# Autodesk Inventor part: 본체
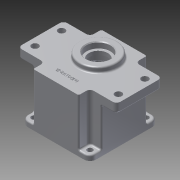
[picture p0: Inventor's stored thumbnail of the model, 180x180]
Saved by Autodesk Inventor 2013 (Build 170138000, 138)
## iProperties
Created: 2015-07
Part Number: 본체
Material: 알루미늄 6061
Document SubType Name: Modeling
Designer: user
Density: 1 g/cm^3
Author: user
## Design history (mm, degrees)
sketch "스케치1"
  geometry: L1 (-37, 45)-(37, 45); L2 (45, 37)-(45, -37); L3 (37, -45)-(-37, -45); L4 (-45, -37)-(-45, 37); L5 (-45, 45)-(45, -45); L6 (45, 45)-(-45, -45); A1 r 8 centre (-37, 37) between (-37, 45) and (-45, 37); A2 r 8 centre (37, 37) between (45, 37) and (37, 45); A3 r 8 centre (37, -37) between (37, -45) and (45, -37); A4 r 8 centre (-37, -37) between (-45, -37) and (-37, -45); 1 further point
  constraints: 12 end point, 8 point on circle, 8 point on line, 8 tangent, 4 centre point, 3 equal radius, 2 midpoint, 2 parallel, 1 horizontal, 1 perpendicular
  dimensions: "d0" = 90 distance of L5.end L6.end; "d1" = 90 distance of L6.start L5.end; "d2" = 8 radius of A1
extrude "돌출1" new body sketch "스케치1" distance "d3" = 70; taper "d4" = 0 deg
sketch "스케치2"
  geometry: L1 (30, 35)-(30, 61.465); L2 (35, 30)-(85.912, 30); L3 (30, 61.465)-(85.912, 30); L4 (37, 45)-(-37, 45) reference; L5 (0, 0)-(0, 77.772); L6 (-30, 35)-(-30, 61.465); L7 (-35, 30)-(-85.912, 30); L8 (-30, 61.465)-(-85.912, 30); L9 (0, 0)-(60.456, 0); L10 (30, -35)-(30, -61.465); L11 (30, -61.465)-(85.912, -30); L12 (35, -30)-(85.912, -30); L13 (-30, -61.465)-(-85.912, -30); L14 (-30, -35)-(-30, -61.465); L15 (-35, -30)-(-85.912, -30); A1 r 5 centre (35, 35) between (30, 35) and (35, 30); A2 r 5 centre (-35, 35) between (-35, 30) and (-30, 35); A3 r 5 centre (35, -35) between (35, -30) and (30, -35); A4 r 5 centre (-35, -35) between (-30, -35) and (-35, -30)
  constraints: 28 end point, 15 symmetric about line, 8 point on circle, 4 centre point, 2 perpendicular, 2 tangent, 1 parallel, 3 other
  dimensions: "d7" = 5 radius of A1
extrude "돌출4" cut sketch "스케치2" distance "d15" = 63; taper "d16" = 0 deg
sketch "스케치6"
  geometry: L1 (-60, 30)-(60, 30); L2 (65, 25)-(65, -25); L3 (60, -30)-(-60, -30); L4 (-65, -25)-(-65, 25); L5 (-65, 30)-(65, -30); L6 (65, 30)-(-65, -30); L7 (-55, 17.5)-(55, -17.5); L8 (55, 17.5)-(-55, -17.5); C1 r 4.5 at (55, 17.5); C2 r 4.5 at (-55, 17.5); C3 r 4.5 at (-55, -17.5); C4 r 4.5 at (55, -17.5); A1 r 5 centre (60, 25) between (65, 25) and (60, 30); A2 r 5 centre (-60, 25) between (-60, 30) and (-65, 25); A3 r 5 centre (-60, -25) between (-65, -25) and (-60, -30); A4 r 5 centre (60, -25) between (60, -30) and (65, -25); 1 further point
  constraints: 16 end point, 8 centre point, 8 point on circle, 8 point on line, 8 tangent, 4 coincident, 4 midpoint, 3 equal radius, 2 parallel, 1 horizontal, 1 perpendicular
  dimensions: "d17" = 130 distance of L5.end L6.end; "d18" = 60 distance of L6.start L5.end; "d19" = 5 radius of A1; "d20" = 110 distance of L7.end L8.end; "d21" = 35 distance of L8.start L7.end; "d22" = 9 diameter of C1; "d23" = 9 diameter of C2; "d24" = 9 diameter of C3; "d25" = 9 diameter of C4
extrude "돌출5" join sketch "스케치6" distance "d26" = 12; taper "d27" = 0 deg
sketch "스케치7"
  geometry: C1 r 3.5 at (-37, 37); C2 r 3.5 at (37, 37); C3 r 3.5 at (-37, -37); C4 r 3.5 at (37, -37); A1 r 8 centre (37, 37) between (45, 37) and (37, 45) reference; A2 r 8 centre (-37, 37) between (-37, 45) and (-45, 37) reference; A3 r 8 centre (-37, -37) between (-45, -37) and (-37, -45) reference; A4 r 8 centre (37, -37) between (37, -45) and (45, -37) reference; 1 further point
  constraints: 4 centre point, 4 coincident
  dimensions: "d28" = 7 diameter of C1; "d29" = 7 diameter of C2; "d30" = 7 diameter of C3; "d31" = 7 diameter of C4
extrude "돌출6" cut sketch "스케치7" stored distance "d32" = 12; taper "d33" = 0 deg
sketch "스케치8"
  geometry: C1 r 40 at (0, 0); 1 further point
  constraints: 1 centre point, 1 coincident
  dimensions: "d34" = 80 diameter of C1
extrude "돌출7" cut sketch "스케치8" distance "d35" = 9; taper "d36" = 0 deg
sketch "스케치9"
  geometry: C1 r 40 at (0, 0) reference; C2 r 39 at (0, 0)
  constraints: 1 centre point, 1 coincident
  dimensions: "d37" = 78 diameter of C2
extrude "돌출8" cut sketch "스케치9" distance "d38" = 52; taper "d39" = 0 deg
sketch "스케치10"
  geometry: L1 (0, 0)-(0, 11); L2 (0, 0)-(0, -20); C1 r 39 at (0, 0) reference; A1 r 20.5 centre (0, 11) between (11.115, -6.225) and (-11.115, -6.225); A2 r 14 centre (0, -20) between (-10.493, -10.732) and (10.493, -10.732); A3 r 3 centre (-12.742, -8.746) between (-10.493, -10.732) and (-11.115, -6.225); A4 r 3 centre (12.742, -8.746) between (11.115, -6.225) and (10.493, -10.732)
  constraints: 8 point on circle, 4 centre point, 4 end point, 4 tangent, 2 coincident, 1 collinear, 1 equal radius, 1 vertical
  dimensions: "d40" = 11 distance of L1.start L1.end; "d41" = 41 diameter of A1; "d45" = 20 distance of L1.start L2.end; "d46" = 28 diameter of A2; "d47" = 3 radius of A3
extrude "돌출9" join sketch "스케치10" distance "d42" = 7; taper "d43" = 0 deg
sketch "스케치12"
  geometry: C1 r 17.5 at (0, 11); A1 r 20.5 centre (0, 11) between (11.115, -6.225) and (-11.115, -6.225) reference; 1 further point
  constraints: 1 centre point, 1 coincident
  dimensions: "d48" = 35 diameter of C1
sketch "스케치13"
  geometry: L1 (60, 30)-(35, 30) reference; L2 (0, 0)-(0, 11); C1 r 25 at (0, 11)
  constraints: 2 end point, 1 centre point, 1 coincident, 1 perpendicular
  dimensions: "d50" = 11 distance of L2.start L2.end; "d51" = 50 diameter of C1
extrude "돌출10" join sketch "스케치13" distance "d52" = 7; taper "d53" = 0 deg
extrude "돌출11" cut sketch "스케치12" distance "d54" = 10; taper "d55" = 0 deg
sketch "스케치14"
  geometry: C1 r 17.5 at (0, 0) reference; C2 r 12.5 at (0, 0); 1 further point
  constraints: 1 centre point, 1 coincident
  dimensions: "d56" = 25 diameter of C2
extrude "돌출12" cut sketch "스케치14" distance "d57" = 5; taper "d58" = 0 deg
sketch "스케치15"
  geometry: C1 r 16 at (0, 0); 1 further point
  constraints: 1 centre point
  dimensions: "d59" = 32 diameter of C1
extrude "돌출13" cut sketch "스케치15" distance "d60" = 8; taper "d61" = 0 deg
sketch "스케치16"
  geometry: C1 r 11 at (0, -20); A1 r 14 centre (0, -20) between (-10.493, -10.732) and (10.493, -10.732) reference; 1 further point
  constraints: 1 centre point, 1 coincident
  dimensions: "d62" = 22 diameter of C1
extrude "돌출14" cut sketch "스케치16" distance "d63" = 7; taper "d64" = 0 deg
sketch "스케치17"
  geometry: C1 r 11 at (0, 0) reference; C2 r 9.5 at (0, 0); 1 further point
  constraints: 1 centre point, 1 coincident
  dimensions: "d65" = 19 diameter of C2
extrude "돌출15" cut sketch "스케치17" distance "d66" = 1; taper "d67" = 0 deg
fillet "모깎기1" dims "d68" = 2
fillet "모깎기2" dims "d69" = 0.3
chamfer "모따기1" distance "d70" = 1; stored, may be unused: second distance "d71" = 2, angle "d72" = 45 deg
sketch "스케치18"
  geometry: L1 (0, 0)-(31.909, 0); L2 (0, 0)-(24.749, 24.749); C1 r 40 at (0, 0) reference; A1 r 39 centre (0, 0) between (21.134, 32.777) and (32.777, 21.134) reference; A2 r 4 centre (24.749, 24.749) between (21.809, 27.462) and (27.462, 21.809); A3 r 3.5 centre (19.238, 29.836) between (21.809, 27.462) and (21.134, 32.777); A4 r 3.5 centre (29.836, 19.238) between (32.777, 21.134) and (27.462, 21.809); A5 r 39 centre (0, 0) between (32.777, 21.134) and (21.134, 32.777)
  constraints: 10 point on circle, 4 centre point, 4 end point, 2 coincident, 2 tangent, 1 concentric, 1 horizontal, 1 symmetric about line, 1 other
  dimensions: "d74" = 35 distance of L1.start L2.end; "d75" = 45 deg angle of L1 L2; "d76" = 8 diameter of A2; "d77" = 7 diameter of A3
extrude "돌출16" join sketch "스케치18" stored distance "d78" = 1; taper "d79" = 0 deg
sketch "스케치19"
  geometry: L1 (-30, -45)-(30, -45) reference; L2 (60, 30)-(35, 30) reference; L3 (0, -45)-(0, -30); 2 further points
  constraints: 2 end point, 1 coincident, 1 midpoint, 1 perpendicular, 1 other
  dimensions: "d83" = 15 distance of L3.start L3.end
feature "엠보싱1" sketch "스케치19" dims "d0" = 90, "d1" = 90, "d2" = 8, "d84" = 0.5, "d85" = 0
fillet "모깎기3" dims "d86" = 2
fillet "모깎기4" dims "d87" = 2
fillet "모깎기5" dims "d88" = 2
fillet "모깎기6" dims "d89" = 2
fillet "모깎기7" dims "d90" = 2
fillet "모깎기8" dims "d91" = 2
sketch "스케치20"
  geometry: A1 r 4 centre (24.749, 24.749) between (21.809, 27.462) and (27.462, 21.809) reference
hole "구멍1" sketch "스케치20" at (24.749, 24.749) diameter "d92" = 3.459; stored, may be unused: countersink angle "d96" = 90 deg, drill point angle "d98" = 118 deg; dims "d93" = 12, "d94" = 4, "d95" = 2, "d97" = 15
node "솔리드1"
pattern_circular "원형 패턴2" dims angle "d81" = 360 deg
pattern_circular "원형 패턴3" dims angle "d100" = 360 deg
